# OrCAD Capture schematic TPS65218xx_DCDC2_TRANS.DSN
size E; title: TPS65218D0 Power Management for ARM® Cortex™-A8/A9; rev: 1.0; note: Datasheet:SLDS234B     EVM:NA; note: Synchronous Step Down Converter
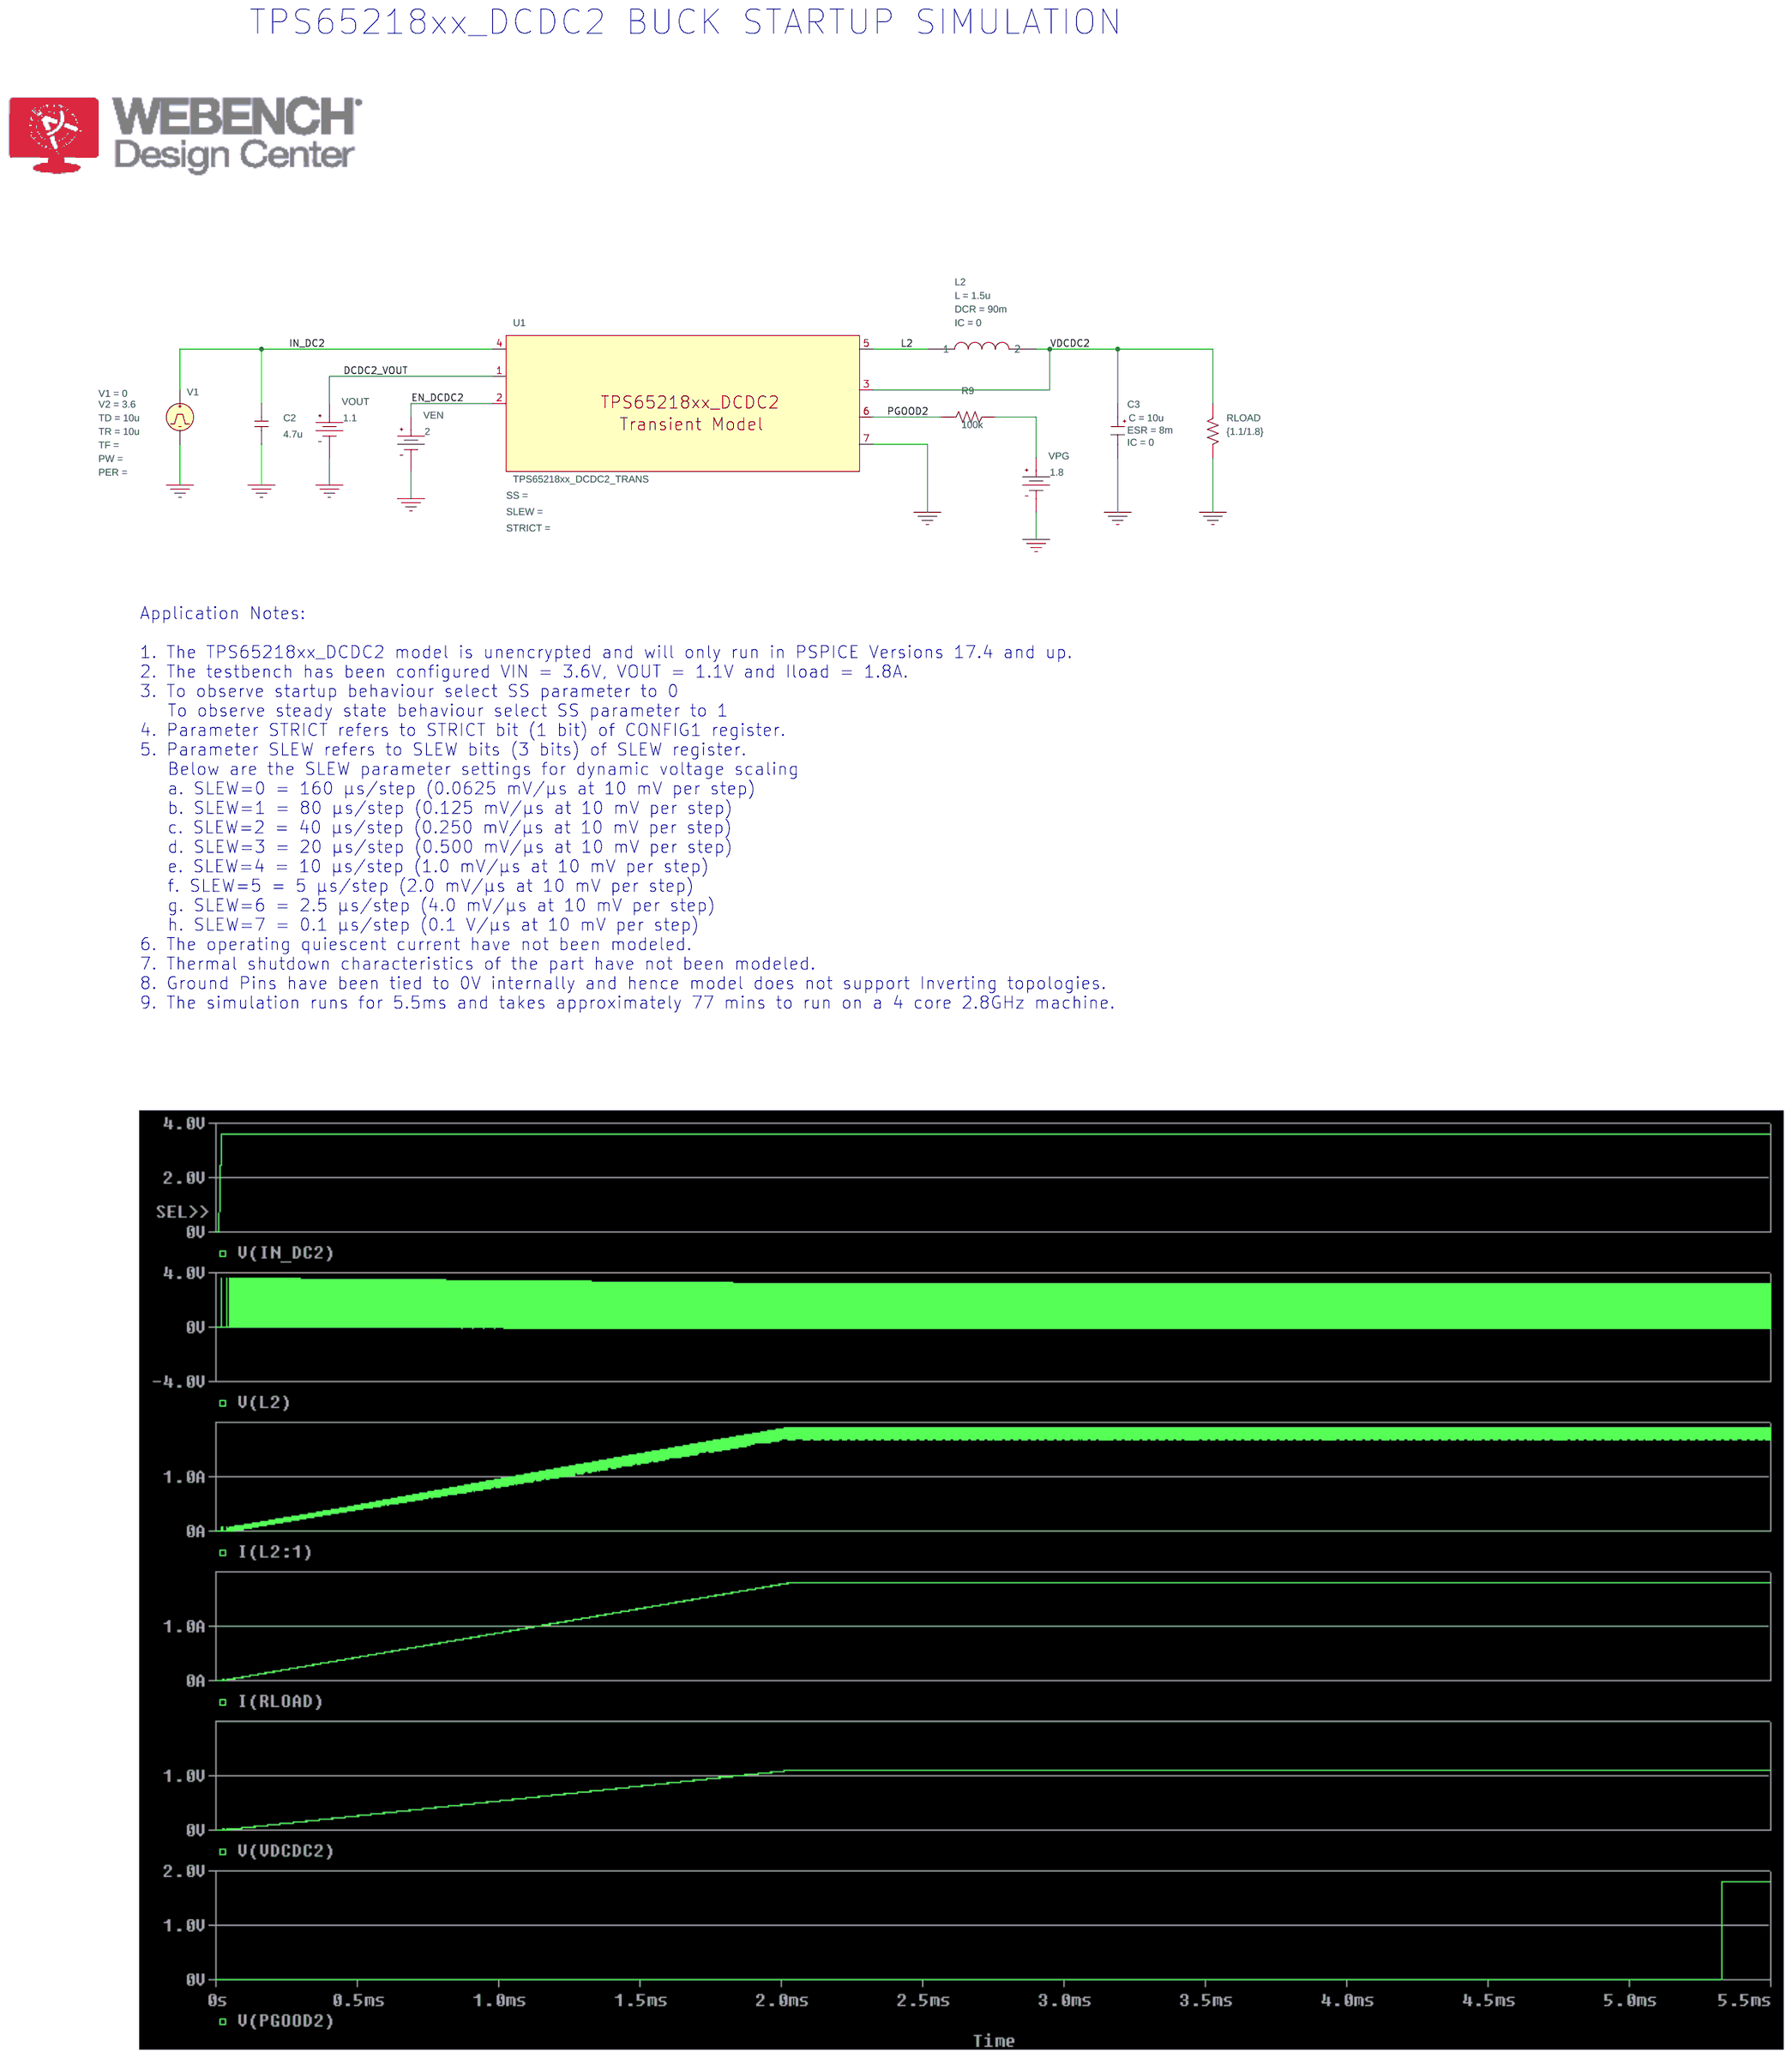
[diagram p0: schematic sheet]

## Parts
C2  4.7u  [RAD/CK05]
C3  CESR
L2  LDCR
R9  100k  [AX/RC05]
RLOAD  {1.1/1.8}  [AX/RC05]
U1  TPS65218xx_DCDC2_TRANS
V1  VPULSE
VEN  VDC
VOUT  VDC
VPG  VDC

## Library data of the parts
C2 = C
C3 = CESR_0: C: 10u; ESR: 8m; IC: 0; PSpiceTemplate: X^@REFDES %IN %OUT @MODEL PARAMS:  ?C|C=@C||C=100u|  ?ESR|ESR=@ESR||ESR=0.01| ?X|X=@X||X=2|  ?IC|IC=@IC||IC=2|; X: 1
L2 = LDCR: DCR: 90m; IC: 0; L: 1.5u
R9 RLOAD = R
U1 = TPS65218XX_DCDC2_TRANS
V1 = VPULSE: TD: 10u; TR: 10u; V1: 0; V2: 3.6
VEN = VDC: DC: 2
VOUT = VDC: DC: 1.1
VPG = VDC: DC: 1.8

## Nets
0: C2.1 C3.2(OUT) RLOAD.2 U1.7(POWER_PAD) V1.2(-) VEN.1(-) VOUT.1(-) VPG.1(-)
DCDC2_VOUT: U1.1(DCDC2_VOUT) VOUT.0(+)
EN_DCDC2: U1.2(EN_DCDC2) VEN.0(+)
IN_DC2: C2.2 U1.4(IN_DCDC2) V1.1(+)
L2: L2.1 U1.5(L2)
PGOOD2: R9.1 U1.6(PGOOD2)
VDCDC2: C3.1(IN) L2.2 RLOAD.1 U1.3(FB2)
N16664947: R9.2 VPG.0(+)

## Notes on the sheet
- TPS65218xx_DCDC2 BUCK STARTUP SIMULATION
- Application Notes:
  1. The TPS65218xx_DCDC2 model is unencrypted and will only run in PSPICE Versions 17.4 and up.
  2. The testbench has been configured VIN = 3.6V, VOUT = 1.1V and Iload = 1.8A.
  3. To observe startup behaviour select SS parameter to 0
     To observe steady state behaviour select SS parameter to 1
  4. Parameter STRICT refers to STRICT bit (1 bit) of CONFIG1 register.
  5. Parameter SLEW refers to SLEW bits (3 bits) of SLEW register.
     Below are the SLEW parameter settings for dynamic voltage scaling
     a. SLEW=0 = 160 µs/step (0.0625 mV/µs at 10 mV per step)
     b. SLEW=1 = 80 µs/step (0.125 mV/µs at 10 mV per step)
     c. SLEW=2 = 40 µs/step (0.250 mV/µs at 10 mV per step)
     d. SLEW=3 = 20 µs/step (0.500 mV/µs at 10 mV per step)
     e. SLEW=4 = 10 µs/step (1.0 mV/µs at 10 mV per step)
     f. SLEW=5 = 5 µs/step (2.0 mV/µs at 10 mV per step)
     g. SLEW=6 = 2.5 µs/step (4.0 mV/µs at 10 mV per step)
     h. SLEW=7 = 0.1 µs/step (0.1 V/µs at 10 mV per step)
  6. The operating quiescent current have not been modeled.
  7. Thermal shutdown characteristics of the part have not been modeled.
  8. Ground Pins have been tied to 0V internally and hence model does not support Inverting topologies.
  9. The simulation runs for 5.5ms and takes approximately 77 mins to run on a 4 core 2.8GHz machine.
